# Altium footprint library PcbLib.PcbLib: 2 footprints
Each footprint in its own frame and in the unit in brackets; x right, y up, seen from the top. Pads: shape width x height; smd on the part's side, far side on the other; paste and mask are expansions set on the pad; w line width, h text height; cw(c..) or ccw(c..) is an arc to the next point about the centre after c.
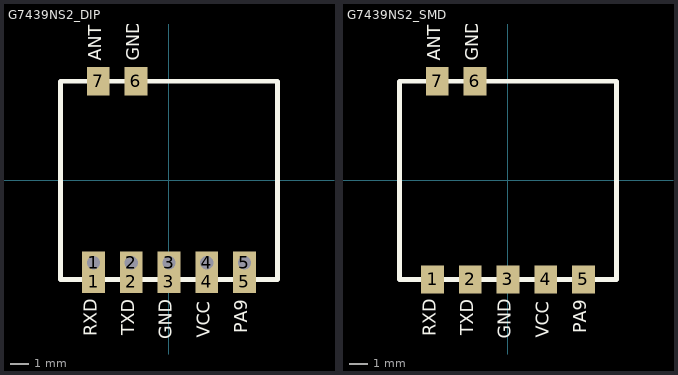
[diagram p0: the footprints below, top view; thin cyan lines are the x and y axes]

## G7439NS2_DIP [mm]
pads (12):
  rect 1.2x1.2 smd: 1(-4,-5.377) 2(-2,-5.377) 3(0,-5.377) 4(2,-5.377) 5(4,-5.377)
  rect 1.2x1.2 hole 0.7: 1(-4,-4.361) 2(-2,-4.361) 3(0,-4.361) 4(2,-4.361) 5(4,-4.361)
  rect 1.2x1.5 smd: 6(-1.75,5.25) 7(-3.75,5.25)
Top Overlay:
  lines w0.254: -5.75,-5.25 5.75,-5.25 5.75,5.25 -5.75,5.25 -5.75,-5.25
  text "RXD" at -3.596,-8.264 h1.14
  text "TXD" at -1.596,-8.203 h1.14
  text "GND" at 0.39,-8.404 h1.14
  text "VCC" at 2.391,-8.337 h1.14
  text "PA9" at 4.39,-8.099 h1.14
  text "ANT" at -3.346,6.349 h1.14
  text "GND" at -1.346,6.334 h1.14

## G7439NS2_SMD [mm]
pads (7):
  rect 1.2x1.5 smd: 1(-4,-5.25) 2(-2,-5.25) 3(0,-5.25) 4(2,-5.25) 5(4,-5.25) 6(-1.75,5.25) 7(-3.75,5.25)
Top Overlay:
  lines w0.254: -5.75,-5.25 -5.75,5.25 5.75,5.25 5.75,-5.25 -5.75,-5.25
  text "GND" at -1.346,6.334 h1.14
  text "ANT" at -3.346,6.349 h1.14
  text "PA9" at 4.39,-8.099 h1.14
  text "VCC" at 2.391,-8.337 h1.14
  text "GND" at 0.39,-8.404 h1.14
  text "TXD" at -1.596,-8.203 h1.14
  text "RXD" at -3.596,-8.264 h1.14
